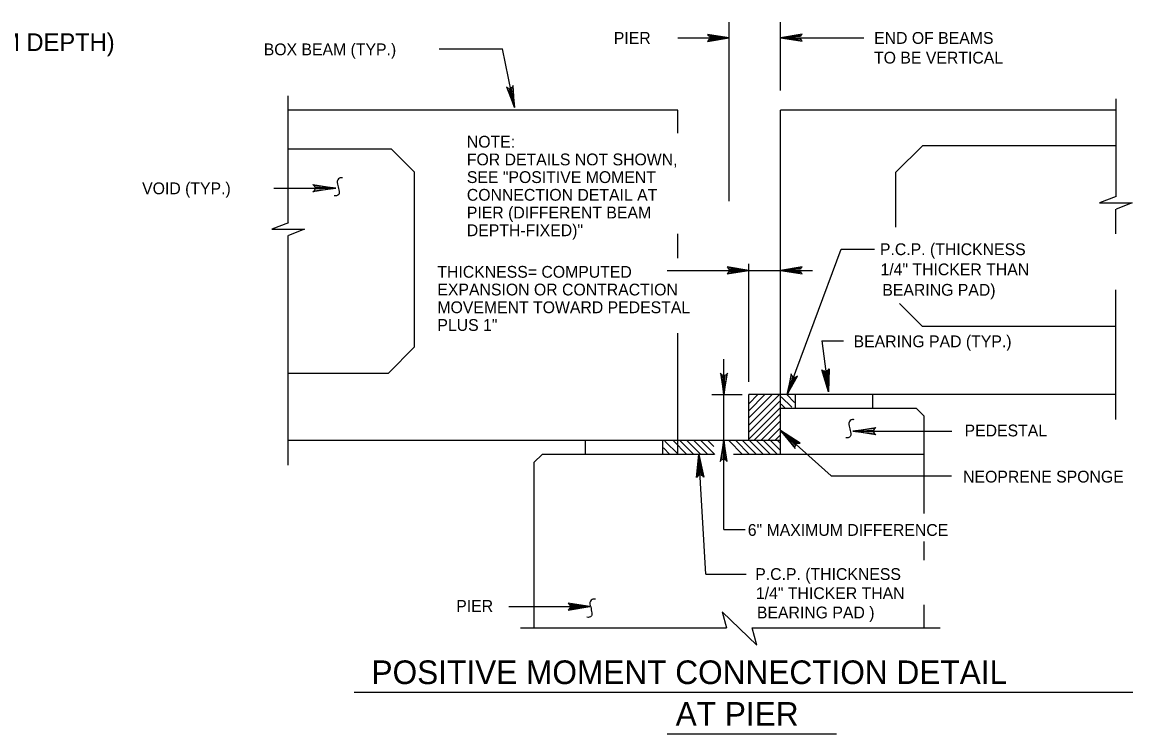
# Model space of a CAD drawing. Extents: x 641517 to 642372, y 298537 to 300319.
# Drawn here: x 641720.5 to 642002.4, y 299332 to 299512.7 of the extents above; entities that cross this region are included whole.
import ezdxf

# ---------------------------------------------------------------- set-up
doc = ezdxf.new("R2010")
doc.units = 0
for name, color, linetype in [('1', 7, 'Continuous'), ('2', 7, 'Continuous'), ('3', 7, 'Continuous')]:
    doc.layers.add(name, color=color, linetype=linetype)

msp = doc.modelspace()

# ---------------------------------------------------------------- linework, layer by layer
at = {"layer": '1'}
for p, q in [((641899.95, 299467.32), (641899.95, 299512.74)), ((641886.92, 299484.58), (641886.92, 299490.36)), ((641912.97, 299402.95), (641912.97, 299490.36)), ((641886.92, 299452.76), (641886.92, 299458.99)), ((641886.92, 299406.47), (641886.92, 299433.79)), ((641916.8, 299414.62), (641916.8, 299418.14)), ((641883.12, 299402.95), (641883.12, 299406.47)), ((641886.92, 299402.95), (641886.92, 299406.47)), ((641906.96, 299354.46), (641898.13, 299362.99)), ((641898.13, 299362.99), (641899.28, 299358.93)), ((641906.96, 299354.46), (641905.77, 299358.93))]:
    msp.add_line(p, q, dxfattribs=at)
for points in [[(641801.8, 299473.22), (641801, 299473.16), (641800.56, 299472.74), (641800.39, 299471.98), (641800.61, 299471.26), (641800.76, 299470.5), (641800.89, 299469.74), (641800.8, 299468.98), (641800.24, 299468.65), (641799.63, 299468.65)], [(641931.68, 299411.77), (641930.87, 299411.7), (641930.44, 299411.29), (641930.27, 299410.53), (641930.48, 299409.81), (641930.63, 299409.05), (641930.77, 299408.28), (641930.68, 299407.52), (641930.11, 299407.2), (641929.5, 299407.2)], [(641865.97, 299366.16), (641865.16, 299366.1), (641864.73, 299365.68), (641864.55, 299364.92), (641864.77, 299364.2), (641864.92, 299363.44), (641865.05, 299362.68), (641864.97, 299361.92), (641864.4, 299361.59), (641863.79, 299361.59)]]:
    msp.add_spline(points, degree=3, dxfattribs=at)
at = {"layer": '2'}
for p, q in [((641912.97, 299495.38), (641912.97, 299512.74)), ((641886.92, 299508.75), (641899.95, 299508.75)), ((641912.97, 299508.81), (641934.12, 299508.81)), ((641826.33, 299505.94), (641842.37, 299505.94)), ((641845.41, 299491.11), (641842.37, 299505.94)), ((641787.97, 299461.81), (641787.97, 299494.03)), ((641998.14, 299468.5), (641998.14, 299493.29)), ((641886.92, 299490.36), (641787.97, 299490.36)), ((641998.14, 299490.36), (641912.97, 299490.36)), ((641814.21, 299480.52), (641787.97, 299480.52)), ((641948.99, 299481.37), (641942.27, 299474.65)), ((641998.14, 299481.37), (641948.99, 299481.37)), ((641784.29, 299470.59), (641800.06, 299470.59)), ((641998.14, 299468.5), (641993.95, 299466.87)), ((641993.95, 299466.87), (642002.2, 299466.87)), ((642002.2, 299466.87), (641998.14, 299465.28)), ((641998.08, 299458.95), (641998.08, 299465.28)), ((641788.04, 299461.81), (641783.85, 299460.18)), ((641783.85, 299460.18), (641792.1, 299460.18)), ((641787.97, 299400.22), (641787.97, 299458.59)), ((641792.1, 299460.18), (641788.04, 299458.59)), ((641914.61, 299418.15), (641928.36, 299455.11)), ((641928.36, 299455.11), (641936.8, 299455.11)), ((641884.22, 299449.69), (641904.89, 299449.69)), ((641904.89, 299421.4), (641904.89, 299451.4)), ((641904.89, 299449.69), (641912.97, 299449.69)), ((641912.97, 299449.69), (641921.04, 299449.69)), ((641998.08, 299411.82), (641998.08, 299444.78)), ((641998.08, 299435.45), (641948.99, 299435.45)), ((641820.08, 299430.24), (641813.35, 299423.52)), ((641923.43, 299431.83), (641928.96, 299431.83)), ((641923.43, 299431.83), (641925.11, 299418.81)), ((641898.61, 299418.05), (641898.61, 299427.13)), ((641813.35, 299423.52), (641787.97, 299423.52)), ((641895.54, 299418.14), (641903.23, 299418.14)), ((641898.61, 299405.26), (641898.61, 299418.05)), ((641904.89, 299406.47), (641904.89, 299418.14)), ((641998.08, 299418.14), (641904.89, 299418.14)), ((641912.66, 299418.14), (641904.89, 299410.37)), ((641910.82, 299418.14), (641904.89, 299412.21)), ((641909, 299418.14), (641904.89, 299414.03)), ((641907.24, 299418.14), (641904.89, 299415.79)), ((641912.97, 299416.67), (641904.89, 299408.6)), ((641915.8, 299414.94), (641913.13, 299417.62)), ((641914.06, 299414.81), (641913.15, 299415.72)), ((641916.53, 299416.15), (641914.53, 299418.14)), ((641936.4, 299414.62), (641936.4, 299418.14)), ((641912.97, 299414.88), (641904.89, 299406.8)), ((641912.97, 299413.23), (641906.21, 299406.47)), ((641947.47, 299414.62), (641912.97, 299414.62)), ((641949.43, 299412.66), (641947.47, 299414.62)), ((641912.97, 299411.46), (641907.97, 299406.47)), ((641949.43, 299387.91), (641949.43, 299412.66)), ((641912.97, 299409.7), (641909.74, 299406.47)), ((641912.97, 299407.93), (641911.51, 299406.47)), ((641912.97, 299409.03), (641925.8, 299397.5)), ((641931.35, 299408.86), (641956.43, 299408.86)), ((641912.97, 299406.47), (641787.97, 299406.47)), ((641863.49, 299402.95), (641863.49, 299406.47)), ((641884.9, 299402.95), (641883.26, 299404.6)), ((641887.05, 299402.95), (641883.63, 299406.36)), ((641889.19, 299402.95), (641885.67, 299406.47)), ((641890.96, 299402.95), (641887.44, 299406.47)), ((641892.72, 299402.95), (641889.2, 299406.47)), ((641894.49, 299402.95), (641890.97, 299406.47)), ((641896.26, 299402.95), (641892.74, 299406.47)), ((641896, 299404.98), (641894.51, 299406.47)), ((641898.61, 299383.89), (641898.61, 299405.26)), ((641903.33, 299402.95), (641899.81, 299406.47)), ((641905.1, 299402.95), (641901.58, 299406.47)), ((641906.87, 299402.95), (641903.34, 299406.47)), ((641908.63, 299402.95), (641905.11, 299406.47)), ((641910.4, 299402.95), (641906.88, 299406.47)), ((641912.17, 299402.95), (641908.65, 299406.47)), ((641912.97, 299403.92), (641910.42, 299406.47)), ((641912.97, 299405.69), (641912.18, 299406.47)), ((641850.46, 299401), (641852.42, 299402.95)), ((641895.99, 299402.95), (641852.42, 299402.95)), ((641894.01, 299372.54), (641892.25, 299402.95)), ((641949.43, 299402.95), (641901.03, 299402.95)), ((641850.46, 299358.93), (641850.46, 299401)), ((641925.8, 299397.5), (641956.33, 299397.5)), ((641898.61, 299383.89), (641903.98, 299383.89)), ((641949.43, 299376.1), (641949.43, 299380.83)), ((641894.01, 299372.54), (641904.22, 299372.54)), ((641843.97, 299364.29), (641864.52, 299364.29)), ((641949.43, 299358.93), (641949.43, 299364.73)), ((641949.43, 299358.93), (641949.43, 299363.8)), ((641846.94, 299358.93), (641899.28, 299358.93)), ((641905.77, 299358.93), (641953.49, 299358.93)), ((641804.76, 299342.57), (642002.39, 299342.57)), ((641884.21, 299331.98), (641927.15, 299331.98))]:
    msp.add_line(p, q, dxfattribs=at)
for points in [[(641894.71, 299508.09), (641894.91, 299508.47), (641899.95, 299508.75), (641894.71, 299508.09), (641894.45, 299507.86), (641899.95, 299508.75), (641894.91, 299509), (641894.73, 299509.37), (641899.95, 299508.75), (641894.45, 299509.62), (641894.73, 299509.37)], [(641918.2, 299509.47), (641918, 299509.09), (641912.97, 299508.81), (641918.2, 299509.47), (641918.47, 299509.7), (641912.97, 299508.81), (641918, 299508.56), (641918.18, 299508.19), (641912.97, 299508.81), (641918.47, 299507.94), (641918.18, 299508.19)], [(641843.68, 299496.09), (641844.1, 299495.98), (641845.41, 299491.11), (641843.68, 299496.09), (641843.4, 299496.31), (641845.41, 299491.11), (641844.61, 299496.08), (641844.94, 299496.34), (641845.41, 299491.11), (641845.13, 299496.67), (641844.94, 299496.34)], [(641794.52, 299471.28), (641794.73, 299470.88), (641800.06, 299470.59), (641794.52, 299471.28), (641794.24, 299471.52), (641800.06, 299470.59), (641794.73, 299470.32), (641794.54, 299469.93), (641800.06, 299470.59), (641794.24, 299469.66), (641794.54, 299469.93)], [(641899.66, 299449.03), (641899.85, 299449.41), (641904.89, 299449.69), (641899.66, 299449.03), (641899.39, 299448.8), (641904.89, 299449.69), (641899.86, 299449.94), (641899.67, 299450.31), (641904.89, 299449.69), (641899.39, 299450.56), (641899.67, 299450.31)], [(641918.2, 299450.35), (641918, 299449.97), (641912.97, 299449.69), (641918.2, 299450.35), (641918.47, 299450.58), (641912.97, 299449.69), (641918, 299449.44), (641918.18, 299449.07), (641912.97, 299449.69), (641918.47, 299448.82), (641918.18, 299449.07)], [(641925.09, 299424.39), (641924.72, 299424.14), (641925.11, 299418.81), (641925.09, 299424.39), (641925.3, 299424.7), (641925.11, 299418.81), (641924.17, 299424.06), (641923.75, 299424.2), (641925.11, 299418.81), (641923.45, 299424.47), (641923.75, 299424.2)], [(641897.95, 299423.28), (641898.33, 299423.09), (641898.61, 299418.05), (641897.95, 299423.28), (641897.72, 299423.55), (641898.61, 299418.05), (641898.86, 299423.09), (641899.23, 299423.27), (641898.61, 299418.05), (641899.48, 299423.55), (641899.23, 299423.27)], [(641915.77, 299423.09), (641916.05, 299422.78), (641914.61, 299418.15), (641915.77, 299423.09), (641915.66, 299423.4), (641914.61, 299418.15), (641916.52, 299422.6), (641916.92, 299422.64), (641914.61, 299418.15), (641917.24, 299422.81), (641916.92, 299422.64)], [(641917.55, 299405.84), (641917.13, 299405.68), (641912.97, 299409.03), (641917.55, 299405.84), (641917.92, 299405.84), (641912.97, 299409.03), (641916.75, 299405.27), (641916.63, 299404.85), (641912.97, 299409.03), (641916.68, 299404.45), (641916.63, 299404.85)], [(641936.89, 299408.17), (641936.68, 299408.57), (641931.35, 299408.86), (641936.89, 299408.17), (641937.17, 299407.93), (641931.35, 299408.86), (641936.68, 299409.13), (641936.87, 299409.52), (641931.35, 299408.86), (641937.17, 299409.79), (641936.87, 299409.52)], [(641899.2, 299401.44), (641898.82, 299401.63), (641898.55, 299406.67), (641899.2, 299401.44), (641899.43, 299401.17), (641898.55, 299406.67), (641898.3, 299401.64), (641897.92, 299401.45), (641898.55, 299406.67), (641897.67, 299401.17), (641897.92, 299401.45)], [(641891.87, 299397.39), (641892.26, 299397.61), (641892.25, 299402.95), (641891.87, 299397.39), (641891.65, 299397.09), (641892.25, 299402.95), (641892.82, 299397.65), (641893.22, 299397.48), (641892.25, 299402.95), (641893.51, 299397.2), (641893.22, 299397.48)], [(641859.29, 299363.63), (641859.49, 299364.01), (641864.52, 299364.29), (641859.29, 299363.63), (641859.02, 299363.4), (641864.52, 299364.29), (641859.49, 299364.54), (641859.31, 299364.91), (641864.52, 299364.29), (641859.02, 299365.16), (641859.31, 299364.91)]]:
    msp.add_lwpolyline(points, dxfattribs=at)
at = {"layer": '3'}
for p, q in [((641820.08, 299474.65), (641814.21, 299480.52)), ((641820.08, 299437.27), (641820.08, 299474.65)), ((641942.27, 299460.67), (641942.27, 299474.65)), ((641948.99, 299435.45), (641943.13, 299441.31)), ((641820.08, 299430.24), (641820.08, 299437.27))]:
    msp.add_line(p, q, dxfattribs=at)

# ---------------------------------------------------------------- texts
at = {"layer": '2'}
for s, height, p in [('(SAME BEAM DEPTH)', 4.5, (641682.07, 299505.41)), ('POSITIVE MOMENT CONNECTION DETAIL', 6, (641809.12, 299344.62)), ('AT PIER', 6, (641886.34, 299334.04))]:
    msp.add_text(s, height=height, dxfattribs=at).set_placement(p)
at = {"layer": '3'}
for s, height, p in [('  PIER', 2.999, (641868.41, 299507.24)), ('END OF BEAMS', 2.9989, (641936.72, 299507.24)), ('BOX BEAM (TYP.)', 2.9968, (641781.77, 299504.34)), ('TO BE VERTICAL', 2.9989, (641936.7, 299502.24)), ('NOTE:', 2.999, (641833.33, 299480.88)), ('FOR DETAILS NOT SHOWN,', 2.9989, (641833.33, 299476.38)), ('SEE "POSITIVE MOMENT', 2.9989, (641833.33, 299471.89)), ('VOID (TYP.)', 2.9968, (641750.9, 299469.04)), ('CONNECTION DETAIL AT', 2.9989, (641833.33, 299467.39)), ('PIER (DIFFERENT BEAM', 2.9989, (641833.33, 299462.89)), ('DEPTH-FIXED)"', 2.9989, (641833.33, 299458.39)), ('P.C.P. (THICKNESS ', 2.9989, (641938.2, 299453.57)), ('THICKNESS= COMPUTED', 2.9989, (641825.85, 299447.83)), ('1/4" THICKER THAN', 2.9989, (641938.34, 299448.45)), ('EXPANSION OR CONTRACTION', 2.9989, (641825.85, 299443.33)), ('BEARING PAD)', 2.9989, (641938.8, 299443.26)), ('MOVEMENT TOWARD PEDESTAL', 2.9989, (641825.85, 299438.83)), ('PLUS 1"', 2.999, (641825.85, 299434.33)), ('BEARING PAD (TYP.)', 2.9989, (641931.5, 299430.17)), ('PEDESTAL', 2.999, (641959.68, 299407.53)), ('NEOPRENE SPONGE', 2.9989, (641959.31, 299395.81)), ('6" MAXIMUM DIFFERENCE', 2.9989, (641904.65, 299382.26)), ('P.C.P. (THICKNESS ', 2.9989, (641906.54, 299371.06)), ('1/4" THICKER THAN', 2.9989, (641906.71, 299366.2)), ('PIER', 2.999, (641830.64, 299362.96)), ('BEARING PAD )', 2.9989, (641906.96, 299361.3))]:
    msp.add_text(s, height=height, dxfattribs=at).set_placement(p)

doc.saveas('drawing.dxf')
